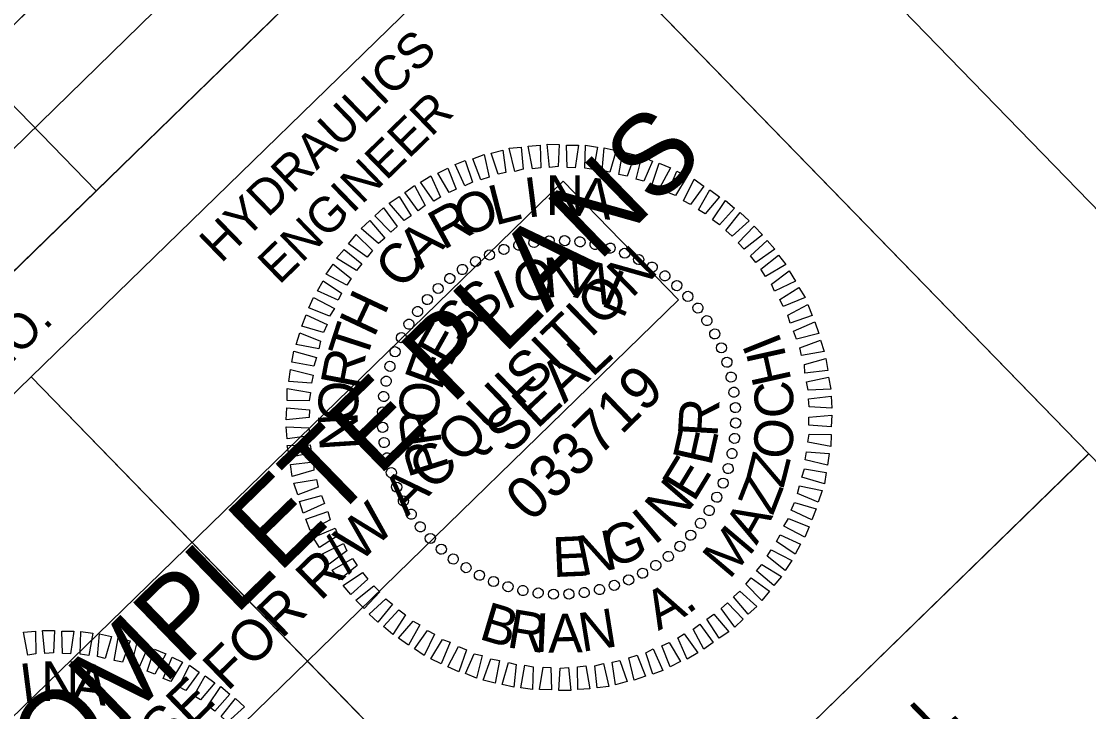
# Model space of a CAD drawing. Extents: x 2010880 to 2012866, y 442935 to 444909.
# Drawn here: x 2012051.6 to 2012203.1, y 444729.3 to 444827.2 of the extents above; entities that cross this region are included whole.
import ezdxf

# ---------------------------------------------------------------- set-up
doc = ezdxf.new("R2010")
doc.units = 0
for name, color, linetype in [('Sheet Plan And Profile CELL', 7, 'Continuous'), ('Sheet Plot Border Outside CELL', 7, 'Continuous'), ('Sheet Professional Seal CELL', 7, 'Continuous'), ('Sheet Profile Grid Minor CELL', 7, 'Continuous'), ('Sheet Sticker Exception Certification CELL', 7, 'Continuous'), ('Sheet Sticker Incomplete CELL', 7, 'Continuous')]:
    doc.layers.add(name, color=color, linetype=linetype)

msp = doc.modelspace()

# ---------------------------------------------------------------- linework, layer by layer
at = {"layer": 'Sheet Plan And Profile CELL'}
for p, q in [((2011963.82, 444724.98), (2012107.25, 444864.44)), ((2011972.54, 444716.02), (2012115.96, 444855.48)), ((2012044.76, 444821.12), (2012062.19, 444803.19)), ((2012052.98, 444776.8), (2012131.37, 444696.18))]:
    msp.add_line(p, q, dxfattribs=at)
for points in [[(2012098.5, 444873.44), (2011023.1, 443827.72), (2011755.1, 443074.95), (2012830.5, 444120.66)], [(2011955.07, 444733.97), (2012098.5, 444873.44), (2012115.96, 444855.48), (2011972.54, 444716.02)], [(2012052.98, 444776.8), (2012124.67, 444846.52), (2012203.1, 444765.86), (2012131.41, 444696.15)], [(2011981.25, 444707.05), (2012052.98, 444776.8), (2012131.41, 444696.15), (2012059.68, 444626.4)]]:
    msp.add_lwpolyline(points, close=True, dxfattribs=at)
at = {"layer": 'Sheet Plot Border Outside CELL'}
msp.add_lwpolyline([(2011647.06, 442935.02), (2012865.85, 444120.17), (2012098.99, 444908.79), (2010880.21, 443723.65)], close=True, dxfattribs=at)
at = {"layer": 'Sheet Professional Seal CELL'}
for p, q in [((2012124.34, 444795.88), (2012124.34, 444795.88)), ((2012126.53, 444796.13), (2012126.53, 444796.13)), ((2012128.69, 444796.14), (2012128.69, 444796.14)), ((2012130.91, 444796), (2012130.91, 444796)), ((2012133.03, 444795.62), (2012133.03, 444795.62)), ((2012118.02, 444794.13), (2012118.02, 444794.13)), ((2012120.08, 444794.88), (2012120.08, 444794.88)), ((2012122.17, 444795.52), (2012122.17, 444795.52)), ((2012135.18, 444795.06), (2012135.18, 444795.06)), ((2012137.26, 444794.35), (2012137.26, 444794.35)), ((2012116.02, 444793.17), (2012116.02, 444793.17)), ((2012139.22, 444793.48), (2012139.22, 444793.48)), ((2012114.2, 444792.03), (2012114.2, 444792.03)), ((2012141.12, 444792.39), (2012141.12, 444792.39)), ((2012142.94, 444791.09), (2012142.94, 444791.09)), ((2012112.42, 444790.78), (2012112.42, 444790.78)), ((2012144.65, 444789.76), (2012144.65, 444789.76)), ((2012110.74, 444789.35), (2012110.74, 444789.35)), ((2012146.22, 444788.22), (2012146.22, 444788.22)), ((2012109.19, 444787.78), (2012109.19, 444787.78)), ((2012147.65, 444786.54), (2012147.65, 444786.54)), ((2012107.86, 444786.07), (2012107.86, 444786.07)), ((2012106.56, 444784.25), (2012106.56, 444784.25)), ((2012148.9, 444784.75), (2012148.9, 444784.75)), ((2012105.48, 444782.35), (2012105.48, 444782.35)), ((2012150.04, 444782.93), (2012150.04, 444782.93)), ((2012151, 444780.94), (2012151, 444780.94)), ((2012104.6, 444780.39), (2012104.6, 444780.39)), ((2012103.9, 444778.31), (2012103.9, 444778.31)), ((2012151.75, 444778.88), (2012151.75, 444778.88)), ((2012103.34, 444776.16), (2012103.34, 444776.16)), ((2012152.39, 444776.78), (2012152.39, 444776.78)), ((2012152.75, 444774.62), (2012152.75, 444774.62)), ((2012102.96, 444774.04), (2012102.96, 444774.04)), ((2012102.82, 444771.82), (2012102.82, 444771.82)), ((2012153, 444772.42), (2012153, 444772.42)), ((2012127.91, 444771.04), (2012127.91, 444771.04)), ((2012153.01, 444770.27), (2012153.01, 444770.27)), ((2012102.82, 444769.66), (2012102.82, 444769.66)), ((2012103.08, 444767.47), (2012103.08, 444767.47)), ((2012152.87, 444768.04), (2012152.87, 444768.04)), ((2012152.49, 444765.93), (2012152.49, 444765.93)), ((2012103.43, 444765.3), (2012103.43, 444765.3)), ((2012104.08, 444763.21), (2012104.08, 444763.21)), ((2012151.93, 444763.78), (2012151.93, 444763.78)), ((2012104.83, 444761.15), (2012104.83, 444761.15)), ((2012151.22, 444761.7), (2012151.22, 444761.7)), ((2012150.35, 444759.73), (2012150.35, 444759.73)), ((2012105.79, 444759.15), (2012105.79, 444759.15)), ((2012149.26, 444757.84), (2012149.26, 444757.84)), ((2012106.93, 444757.33), (2012106.93, 444757.33)), ((2012108.18, 444755.55), (2012108.18, 444755.55)), ((2012147.96, 444756.02), (2012147.96, 444756.02)), ((2012109.6, 444753.87), (2012109.6, 444753.87)), ((2012146.63, 444754.3), (2012146.63, 444754.3)), ((2012111.17, 444752.32), (2012111.17, 444752.32)), ((2012145.09, 444752.73), (2012145.09, 444752.73)), ((2012112.89, 444750.99), (2012112.89, 444750.99)), ((2012143.41, 444751.31), (2012143.41, 444751.31)), ((2012114.71, 444749.69), (2012114.71, 444749.69)), ((2012139.8, 444748.92), (2012139.8, 444748.92)), ((2012141.62, 444750.06), (2012141.62, 444750.06)), ((2012116.6, 444748.61), (2012116.6, 444748.61)), ((2012118.57, 444747.73), (2012118.57, 444747.73)), ((2012135.75, 444747.21), (2012135.75, 444747.21)), ((2012137.81, 444747.96), (2012137.81, 444747.96)), ((2012120.65, 444747.03), (2012120.65, 444747.03)), ((2012122.8, 444746.47), (2012122.8, 444746.47)), ((2012124.91, 444746.09), (2012124.91, 444746.09)), ((2012127.14, 444745.95), (2012127.14, 444745.95)), ((2012129.29, 444745.95), (2012129.29, 444745.95)), ((2012131.49, 444746.21), (2012131.49, 444746.21)), ((2012133.65, 444746.56), (2012133.65, 444746.56))]:
    msp.add_line(p, q, dxfattribs=at)
for points in [[(2012121.61, 444805.92), (2012120.84, 444809.22), (2012122.51, 444809.38), (2012122.82, 444806.26)], [(2012124.13, 444806.28), (2012123.54, 444809.54), (2012125.24, 444809.66), (2012125.3, 444806.44)], [(2012126.57, 444806.49), (2012126.23, 444809.78), (2012127.92, 444809.76), (2012127.77, 444806.62)], [(2012129.08, 444806.49), (2012128.98, 444809.67), (2012130.68, 444809.65), (2012130.18, 444806.44)], [(2012131.59, 444806.42), (2012131.67, 444809.64), (2012133.36, 444809.4), (2012132.79, 444806.19)], [(2012134.02, 444806.07), (2012134.32, 444809.28), (2012136.01, 444808.9), (2012135.12, 444805.81)], [(2012116.82, 444804.75), (2012115.66, 444807.74), (2012117.26, 444808.32), (2012117.99, 444805.13)], [(2012119.27, 444805.53), (2012118.25, 444808.52), (2012119.92, 444808.95), (2012120.37, 444805.76)], [(2012136.39, 444805.5), (2012136.96, 444808.71), (2012138.69, 444808.3), (2012137.58, 444805.28)], [(2012138.85, 444804.83), (2012139.64, 444808.04), (2012141.19, 444807.38), (2012139.94, 444804.57)], [(2012112.31, 444802.94), (2012110.68, 444805.69), (2012112.14, 444806.41), (2012113.3, 444803.42)], [(2012114.55, 444803.87), (2012113.18, 444806.93), (2012114.6, 444807.47), (2012115.62, 444804.42)], [(2012141.07, 444803.99), (2012142.14, 444807.12), (2012143.72, 444806.43), (2012142.19, 444803.55)], [(2012110.13, 444801.74), (2012108.23, 444804.41), (2012109.72, 444805.31), (2012111.06, 444802.29)], [(2012143.35, 444802.93), (2012144.63, 444805.99), (2012146.11, 444805.26), (2012144.44, 444802.53)], [(2012145.6, 444801.77), (2012147.09, 444804.82), (2012148.46, 444803.85), (2012146.58, 444801.26)], [(2012107.92, 444800.35), (2012106.01, 444802.96), (2012107.37, 444803.93), (2012108.89, 444801.08)], [(2012147.7, 444800.47), (2012149.3, 444803.34), (2012150.7, 444802.33), (2012148.65, 444799.92)], [(2012105.92, 444798.97), (2012103.8, 444801.43), (2012105.19, 444802.37), (2012106.92, 444799.66)], [(2012149.7, 444799.06), (2012151.54, 444801.83), (2012152.83, 444800.71), (2012150.68, 444798.34)], [(2012104.02, 444797.33), (2012101.76, 444799.66), (2012102.98, 444800.77), (2012104.92, 444798.13)], [(2012102.27, 444795.69), (2012099.82, 444797.85), (2012101.04, 444798.96), (2012103.16, 444796.49)], [(2012151.59, 444797.55), (2012153.64, 444800.1), (2012154.89, 444798.95), (2012152.49, 444796.76)], [(2012153.36, 444795.79), (2012155.59, 444798.16), (2012156.77, 444796.95), (2012154.2, 444794.93)], [(2012100.65, 444793.77), (2012098.03, 444795.68), (2012099.11, 444797.01), (2012101.41, 444794.71)], [(2012155.07, 444793.96), (2012157.47, 444796.16), (2012158.55, 444794.91), (2012155.84, 444793.03)], [(2012099.14, 444791.88), (2012096.33, 444793.62), (2012097.41, 444794.88), (2012099.9, 444792.83)], [(2012097.8, 444789.81), (2012094.85, 444791.34), (2012095.83, 444792.78), (2012098.38, 444790.73)], [(2012156.56, 444792.07), (2012159.07, 444794.08), (2012160.11, 444792.73), (2012157.22, 444791.03)], [(2012158.06, 444789.96), (2012160.56, 444791.84), (2012161.49, 444790.37), (2012158.5, 444788.93)], [(2012096.53, 444787.68), (2012093.62, 444789.02), (2012094.42, 444790.43), (2012097.04, 444788.66)], [(2012095.34, 444785.39), (2012092.38, 444786.57), (2012093.04, 444788.04), (2012096.02, 444786.48)], [(2012159.26, 444787.79), (2012161.94, 444789.48), (2012162.84, 444788.06), (2012159.71, 444786.76)], [(2012160.4, 444785.54), (2012163.25, 444787.06), (2012163.86, 444785.5), (2012160.74, 444784.41)], [(2012094.49, 444783.11), (2012091.39, 444784), (2012092.01, 444785.58), (2012094.97, 444784.2)], [(2012161.21, 444783.27), (2012164.24, 444784.61), (2012164.78, 444782.97), (2012161.62, 444782.13)], [(2012093.79, 444780.75), (2012090.58, 444781.39), (2012091.13, 444783.05), (2012094.05, 444781.84)], [(2012162.1, 444780.92), (2012165.02, 444782.01), (2012165.56, 444780.38), (2012162.33, 444779.82)], [(2012093.08, 444778.32), (2012089.98, 444778.86), (2012090.25, 444780.44), (2012093.45, 444779.52)], [(2012162.74, 444778.55), (2012165.79, 444779.42), (2012166.05, 444777.72), (2012162.79, 444777.34)], [(2012092.76, 444775.92), (2012089.55, 444776.14), (2012089.78, 444777.83), (2012092.99, 444777.05)], [(2012163.06, 444776.07), (2012166.18, 444776.73), (2012166.51, 444775.03), (2012163.26, 444774.93)], [(2012092.41, 444773.41), (2012089.3, 444773.46), (2012089.32, 444775.15), (2012092.6, 444774.58)], [(2012163.31, 444773.66), (2012166.53, 444774.07), (2012166.65, 444772.37), (2012163.43, 444772.53)], [(2012092.45, 444771.01), (2012089.19, 444770.7), (2012089.28, 444772.4), (2012092.46, 444772.14)], [(2012163.38, 444771.08), (2012166.64, 444771.38), (2012166.54, 444769.69), (2012163.36, 444769.95)], [(2012092.52, 444768.43), (2012089.29, 444768.01), (2012089.18, 444769.71), (2012092.39, 444769.56)], [(2012163.42, 444768.67), (2012166.53, 444768.63), (2012166.5, 444766.93), (2012163.22, 444767.51)], [(2012092.77, 444766.02), (2012089.65, 444765.35), (2012089.32, 444767.06), (2012092.57, 444767.15)], [(2012163.06, 444766.17), (2012166.28, 444765.94), (2012166.04, 444764.25), (2012162.83, 444765.04)], [(2012093.09, 444763.54), (2012090.03, 444762.66), (2012089.77, 444764.36), (2012093.03, 444764.74)], [(2012162.75, 444763.77), (2012165.85, 444763.23), (2012165.58, 444761.64), (2012162.37, 444762.57)], [(2012093.72, 444761.16), (2012090.81, 444760.07), (2012090.27, 444761.7), (2012093.49, 444762.26)], [(2012162.04, 444761.34), (2012165.25, 444760.69), (2012164.69, 444759.04), (2012161.78, 444760.24)], [(2012094.61, 444758.81), (2012091.59, 444757.48), (2012091.04, 444759.11), (2012094.2, 444759.95)], [(2012161.33, 444758.98), (2012164.43, 444758.08), (2012163.81, 444756.5), (2012160.86, 444757.89)], [(2012095.43, 444756.54), (2012092.58, 444755.02), (2012091.96, 444756.59), (2012095.09, 444757.68)], [(2012160.49, 444756.69), (2012163.44, 444755.52), (2012162.79, 444754.04), (2012159.8, 444755.6)], [(2012096.56, 444754.3), (2012093.89, 444752.6), (2012092.99, 444754.03), (2012096.12, 444755.33)], [(2012159.29, 444754.41), (2012162.21, 444753.06), (2012161.41, 444751.66), (2012158.78, 444753.43)], [(2012097.77, 444752.12), (2012095.27, 444750.25), (2012094.33, 444751.71), (2012097.32, 444753.15)], [(2012158.02, 444752.27), (2012160.97, 444750.74), (2012160, 444749.31), (2012157.44, 444751.36)], [(2012099.26, 444750.02), (2012096.76, 444748), (2012095.72, 444749.36), (2012098.6, 444751.05)], [(2012156.69, 444750.2), (2012159.49, 444748.47), (2012158.41, 444747.21), (2012155.93, 444749.26)], [(2012100.75, 444748.12), (2012098.35, 444745.93), (2012097.28, 444747.18), (2012099.99, 444749.05)], [(2012102.46, 444746.29), (2012100.24, 444743.92), (2012099.05, 444745.14), (2012101.62, 444747.15)], [(2012155.17, 444748.31), (2012157.8, 444746.4), (2012156.72, 444745.07), (2012154.42, 444747.37)], [(2012153.56, 444746.39), (2012156, 444744.24), (2012154.78, 444743.12), (2012152.66, 444745.59)], [(2012104.24, 444744.54), (2012102.19, 444741.98), (2012100.93, 444743.13), (2012103.33, 444745.33)], [(2012151.8, 444744.75), (2012154.07, 444742.42), (2012152.85, 444741.31), (2012150.91, 444743.95)], [(2012106.13, 444743.02), (2012104.29, 444740.26), (2012102.99, 444741.37), (2012105.15, 444743.75)], [(2012149.9, 444743.12), (2012152.03, 444740.65), (2012150.63, 444739.71), (2012148.9, 444742.43)], [(2012108.12, 444741.62), (2012106.53, 444738.74), (2012105.13, 444739.75), (2012107.18, 444742.16)], [(2012147.9, 444741.73), (2012149.81, 444739.13), (2012148.46, 444738.15), (2012146.94, 444741)], [(2012052.48, 444737.34), (2012051.89, 444740.6), (2012053.59, 444740.72), (2012053.65, 444737.5)], [(2012054.92, 444737.55), (2012054.58, 444740.84), (2012056.27, 444740.82), (2012056.12, 444737.67)], [(2012057.43, 444737.55), (2012057.33, 444740.73), (2012059.03, 444740.71), (2012058.53, 444737.5)], [(2012059.94, 444737.48), (2012060.02, 444740.7), (2012061.71, 444740.46), (2012061.14, 444737.25)], [(2012062.38, 444737.13), (2012062.67, 444740.34), (2012064.36, 444739.96), (2012063.47, 444736.86)], [(2012064.74, 444736.56), (2012065.31, 444739.77), (2012067.04, 444739.36), (2012065.94, 444736.34)], [(2012110.23, 444740.32), (2012108.74, 444737.26), (2012107.37, 444738.23), (2012109.24, 444740.82)], [(2012112.47, 444739.15), (2012111.19, 444736.09), (2012109.72, 444736.82), (2012111.38, 444739.56)], [(2012145.69, 444740.35), (2012147.6, 444737.67), (2012146.1, 444736.77), (2012144.77, 444739.8)], [(2012067.2, 444735.89), (2012067.99, 444739.1), (2012069.54, 444738.44), (2012068.29, 444735.63)], [(2012069.42, 444735.05), (2012070.49, 444738.18), (2012072.07, 444737.49), (2012070.54, 444734.61)], [(2012114.76, 444738.1), (2012113.69, 444734.96), (2012112.11, 444735.66), (2012113.63, 444738.54)], [(2012141.28, 444738.22), (2012142.65, 444735.16), (2012141.23, 444734.61), (2012140.21, 444737.67)], [(2012143.52, 444739.14), (2012145.14, 444736.4), (2012143.68, 444735.68), (2012142.52, 444738.66)], [(2012071.7, 444733.99), (2012072.98, 444737.05), (2012074.46, 444736.32), (2012072.79, 444733.59)], [(2012116.97, 444737.25), (2012116.19, 444734.04), (2012114.64, 444734.7), (2012115.88, 444737.51)], [(2012119.44, 444736.58), (2012118.86, 444733.37), (2012117.14, 444733.78), (2012118.24, 444736.81)], [(2012136.55, 444736.55), (2012137.57, 444733.57), (2012135.9, 444733.13), (2012135.45, 444736.32)], [(2012139, 444737.33), (2012140.16, 444734.35), (2012138.56, 444733.77), (2012137.83, 444736.96)], [(2012073.95, 444732.83), (2012075.44, 444735.88), (2012076.81, 444734.91), (2012074.93, 444732.32)], [(2012121.8, 444736.02), (2012121.51, 444732.8), (2012119.82, 444733.18), (2012120.71, 444736.28)], [(2012124.24, 444735.66), (2012124.15, 444732.45), (2012122.46, 444732.68), (2012123.04, 444735.89)], [(2012126.74, 444735.59), (2012126.84, 444732.41), (2012125.14, 444732.43), (2012125.65, 444735.64)], [(2012129.26, 444735.59), (2012129.6, 444732.3), (2012127.9, 444732.32), (2012128.05, 444735.47)], [(2012131.7, 444735.81), (2012132.29, 444732.55), (2012130.59, 444732.43), (2012130.53, 444735.65)], [(2012134.21, 444736.16), (2012134.98, 444732.86), (2012133.32, 444732.71), (2012133.01, 444735.82)], [(2012076.05, 444731.53), (2012077.65, 444734.4), (2012079.05, 444733.39), (2012077, 444730.98)], [(2012078.05, 444730.12), (2012079.89, 444732.89), (2012081.18, 444731.77), (2012079.03, 444729.4)], [(2012079.94, 444728.61), (2012081.99, 444731.16), (2012083.24, 444730.01), (2012080.84, 444727.82)]]:
    msp.add_lwpolyline(points, close=True, dxfattribs=at)
for centre, major_axis in [((2012120.08, 444794.87), (-0.225, 0.684)), ((2012122.19, 444795.46), (-0.164, 0.701)), ((2012124.34, 444795.87), (-0.103, 0.713)), ((2012126.51, 444796.08), (-0.04, 0.719)), ((2012128.7, 444796.11), (0.023, 0.72)), ((2012130.88, 444795.95), (0.085, 0.715)), ((2012133.04, 444795.59), (0.147, 0.705)), ((2012135.16, 444795.05), (0.208, 0.689)), ((2012118.03, 444794.09), (-0.284, 0.662)), ((2012137.23, 444794.33), (0.267, 0.669)), ((2012139.22, 444793.43), (0.325, 0.643)), ((2012114.18, 444792.03), (-0.394, 0.602)), ((2012116.06, 444793.15), (-0.34, 0.635)), ((2012141.13, 444792.36), (0.379, 0.612)), ((2012112.4, 444790.75), (-0.445, 0.566)), ((2012142.94, 444791.12), (0.431, 0.577)), ((2012110.74, 444789.33), (-0.493, 0.525)), ((2012144.63, 444789.74), (0.48, 0.537)), ((2012109.22, 444787.76), (-0.537, 0.48)), ((2012146.2, 444788.21), (0.525, 0.493)), ((2012107.83, 444786.07), (-0.577, 0.431)), ((2012147.62, 444786.55), (0.566, 0.445)), ((2012106.6, 444784.26), (-0.612, 0.379)), ((2012148.9, 444784.77), (0.602, 0.394)), ((2012150.02, 444782.89), (0.635, 0.34)), ((2012105.53, 444782.35), (-0.643, 0.325)), ((2012104.63, 444780.36), (-0.669, 0.267)), ((2012150.96, 444780.92), (0.662, 0.284)), ((2012103.9, 444778.29), (-0.689, 0.208)), ((2012151.74, 444778.87), (0.684, 0.225)), ((2012152.33, 444776.77), (0.701, 0.164)), ((2012103.36, 444776.17), (-0.705, 0.147)), ((2012103.01, 444774.01), (-0.715, 0.085)), ((2012152.74, 444774.62), (0.713, 0.103)), ((2012152.95, 444772.44), (0.719, 0.04)), ((2012102.85, 444771.83), (-0.72, 0.023)), ((2012102.87, 444769.64), (-0.719, -0.04)), ((2012152.98, 444770.25), (0.72, -0.023)), ((2012152.82, 444768.07), (0.715, -0.085)), ((2012103.09, 444767.47), (-0.713, -0.103)), ((2012103.5, 444765.32), (-0.701, -0.164)), ((2012152.46, 444765.91), (0.705, -0.147)), ((2012104.09, 444763.21), (-0.684, -0.225)), ((2012151.92, 444763.79), (0.689, -0.208)), ((2012151.2, 444761.73), (0.669, -0.267)), ((2012104.86, 444761.16), (-0.662, -0.284)), ((2012105.81, 444759.19), (-0.635, -0.34)), ((2012150.3, 444759.73), (0.643, -0.325)), ((2012106.93, 444757.31), (-0.602, -0.394)), ((2012149.23, 444757.83), (0.612, -0.379)), ((2012108.2, 444755.53), (-0.566, -0.445)), ((2012147.99, 444756.02), (0.577, -0.431)), ((2012146.61, 444754.33), (0.537, -0.48)), ((2012109.63, 444753.87), (-0.525, -0.493)), ((2012145.08, 444752.76), (0.493, -0.525)), ((2012111.2, 444752.35), (-0.48, -0.537)), ((2012112.89, 444750.96), (-0.431, -0.577)), ((2012143.42, 444751.33), (0.445, -0.566)), ((2012114.7, 444749.73), (-0.379, -0.612)), ((2012141.64, 444750.06), (0.394, -0.602)), ((2012116.6, 444748.66), (-0.325, -0.643)), ((2012137.79, 444747.99), (0.284, -0.662)), ((2012139.76, 444748.94), (0.34, -0.635)), ((2012118.6, 444747.76), (-0.267, -0.669)), ((2012120.66, 444747.03), (-0.208, -0.689)), ((2012122.78, 444746.49), (-0.147, -0.705)), ((2012133.64, 444746.62), (0.164, -0.701)), ((2012135.75, 444747.22), (0.225, -0.684)), ((2012124.94, 444746.14), (-0.085, -0.715)), ((2012127.12, 444745.97), (-0.023, -0.72)), ((2012129.31, 444746), (0.04, -0.719)), ((2012131.49, 444746.22), (0.103, -0.713))]:
    msp.add_ellipse(centre, major_axis=major_axis, ratio=0.999708, dxfattribs=at)
at = {"layer": 'Sheet Sticker Exception Certification CELL'}
msp.add_line((2012059.67, 444626.41), (2012203.09, 444765.87), dxfattribs=at)
at = {"layer": 'Sheet Sticker Incomplete CELL'}
msp.add_lwpolyline([(2012039.5, 444685.24), (2012023.12, 444702.08), (2012128.51, 444804.56), (2012144.89, 444787.72)], close=True, dxfattribs=at)

# ---------------------------------------------------------------- texts
at = {"layer": 'Sheet Plan And Profile CELL'}
for s, height, p in [('HYDRAULICS', 5, (2012079.9, 444792.8)), ('ENGINEER', 5, (2012088.17, 444789.75)), ('R/W SHEET NO.', 5.0001, (2012019.82, 444749.16))]:
    msp.add_text(s, height=height, rotation=44.1983, dxfattribs=at).set_placement(p)
at = {"layer": 'Sheet Professional Seal CELL'}
for s, height, rotation, p in [('I', 5.64, 7.2184, (2012123.39, 444799.36)), ('N', 5.64, 0.0172, (2012126.02, 444799.74)), ('A', 5.64, 352.8154, (2012130.19, 444799.69)), ('O', 5.64, 21.6194, (2012114.37, 444796.51)), ('L', 5.64, 14.4191, (2012118.82, 444798.25)), ('R', 5.64, 28.8193, (2012111.45, 444794.72)), ('A', 5.64, 43.2186, (2012108.3, 444791.93)), ('C', 5.64, 50.4181, (2012105.68, 444788.96)), ('O', 5.64, 14.0317, (2012122.2, 444787.1)), ('N', 5.64, 4.6749, (2012125.99, 444788.01)), ('A', 5.64, 345.9585, (2012129.85, 444788.13)), ('I', 5.64, 23.3879, (2012120.28, 444786.21)), ('L', 5.64, 336.5991, (2012133.65, 444787.01)), ('S', 5.64, 42.0987, (2012116.7, 444783.72)), ('H', 5.64, 64.8177, (2012101.62, 444782.23)), ('S', 5.64, 51.4539, (2012114.16, 444781.17)), ('T', 5.64, 72.018, (2012100.44, 444778.78)), ('E', 5.64, 60.8093, (2012112.42, 444778.01)), ('R', 5.64, 79.2188, (2012099.54, 444774.83)), ('F', 5.64, 70.1653, (2012111.17, 444774.71)), ('SEAL', 5.998, 43.1983, (2012120.87, 444765.59)), ('O', 5.64, 86.42, (2012099.22, 444770.21)), ('O', 5.64, 88.8795, (2012110.86, 444770.29)), ('R', 5.64, 86.6797, (2012150.4, 444768.15)), ('R', 5.64, 98.2379, (2012111.31, 444767.31)), ('N', 5.64, 93.6218, (2012099.6, 444766.52)), ('E', 5.64, 77.3223, (2012149.49, 444763.99)), ('P', 5.64, 107.5971, (2012112.4, 444763.9)), ('E', 5.64, 58.61, (2012147.05, 444758.89)), ('N', 5.64, 49.2546, (2012143.92, 444755.01)), ('I', 5.64, 39.8995, (2012141.41, 444752.79)), ('G', 5.64, 21.1885, (2012135.39, 444749.58)), ('N', 5.64, 11.8322, (2012131.1, 444748.54)), ('E', 5.64, 2.4751, (2012127.07, 444748.39)), ('I', 5.64, 7.2184, (2012051.74, 444730.42)), ('N', 5.64, 0.0172, (2012054.37, 444730.8)), ('A', 5.64, 352.8154, (2012058.54, 444730.75))]:
    msp.add_text(s, height=height, rotation=rotation, dxfattribs=at).set_placement(p)
at = {"layer": 'Sheet Profile Grid Minor CELL'}
for s, height, rotation, p in [('I', 5.5, 111.7909, (2012159.66, 444781.5)), ('H', 5.5, 102.5461, (2012160.93, 444776.26)), ('033719', 5.998, 44.1983, (2012123.95, 444756.02)), ('C', 5.5, 93.6734, (2012161.34, 444771.11)), ('O', 5.5, 82.9689, (2012160.77, 444764.9)), ('Z', 5.5, 75.8421, (2012159.76, 444760.87)), ('Z', 5.5, 68.7153, (2012158.25, 444757)), ('A', 5.5, 60.5295, (2012155.94, 444752.82)), ('M', 5.5, 49.8536, (2012152.08, 444747.95)), ('A', 5.5, 28.4875, (2012142, 444740.73)), ('B', 5.5, 343.3512, (2012116.37, 444739.67)), ('.', 5.5, 36.6733, (2012146.18, 444743.04)), ('R', 5.5, 350.478, (2012120.35, 444738.48)), ('I', 5.5, 357.4044, (2012124.33, 444737.81)), ('A', 5.5, 0.9249, (2012126.38, 444737.65)), ('N', 5.5, 9.1107, (2012131.15, 444737.77))]:
    msp.add_text(s, height=height, rotation=rotation, dxfattribs=at).set_placement(p)
at = {"layer": 'Sheet Sticker Exception Certification CELL'}
msp.add_text('DOCUMENT NOT CONSIDERED FINAL', height=6.124, rotation=44.1983, dxfattribs=at).set_placement((2012077.82, 444624.42))
at = {"layer": 'Sheet Sticker Incomplete CELL'}
for s, height, p in [('INCOMPLETE PLANS', 11.52, (2012037.76, 444699.86)), ('DO NOT USE FOR R/W ACQUISITION', 5.76, (2012044.94, 444697.15))]:
    msp.add_text(s, height=height, rotation=44.1983, dxfattribs=at).set_placement(p)

doc.saveas('drawing.dxf')
